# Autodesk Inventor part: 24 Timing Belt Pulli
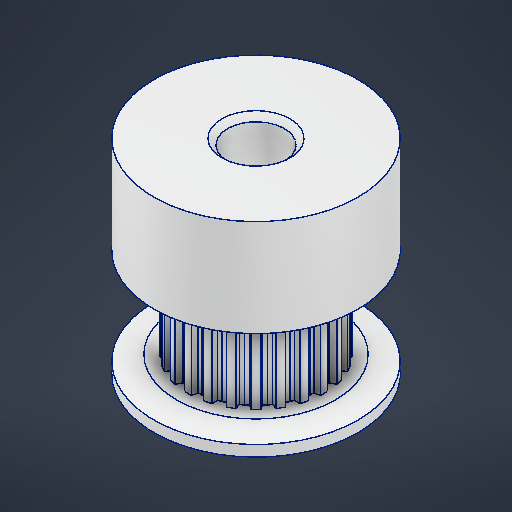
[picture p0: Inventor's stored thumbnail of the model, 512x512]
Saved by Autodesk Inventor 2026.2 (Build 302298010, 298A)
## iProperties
Created: 2026-04
Part Number: 24 Timing Belt Pulli
Material: 알루미늄 6061
Document SubType Name: Modeling
Designer: work
Density: 2.7 g/cm^3
Appearance: 알루미늄 - 평지
Author: work
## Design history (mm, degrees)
sketch "스케치1"
  geometry: C1 r 9 at (0, 0); C2 r 2.5 at (0, 0); 1 further point
  constraints: 2 centre point, 2 coincident
  dimensions: "d0" = 18 diameter of C1; "d1" = 5 diameter of C2
extrude "돌출1" new body sketch "스케치1" distance "d2" = 18; taper "d3" = 0 deg
node "작업 평면1"
sketch "스케치2"
  geometry: L1 (0, 0)-(0, -6); L2 (0, -6)-(0.305, -6); L3 (0.305, -6)-(0.393, -5.5); L4 (0.393, -5.5)-(0.785, -5.5); L5 (0, -6)-(-0.305, -6); L6 (-0.305, -6)-(-0.393, -5.5); L7 (-0.393, -5.5)-(-0.785, -5.5); L8 (0, 0)-(1.553, -5.796); L9 (1.553, -5.796)-(1.847, -5.717); L10 (1.847, -5.717)-(1.803, -5.211); L11 (1.803, -5.211)-(2.182, -5.109); L12 (1.553, -5.796)-(1.259, -5.874); L13 (1.259, -5.874)-(1.044, -5.414); L14 (1.044, -5.414)-(0.665, -5.516); L15 (0, 0)-(3, -5.196); L16 (3, -5.196)-(3.264, -5.044); L17 (3.264, -5.044)-(3.09, -4.567); L18 (3.09, -4.567)-(3.43, -4.37); L19 (3, -5.196)-(2.736, -5.348); L20 (2.736, -5.348)-(2.41, -4.959); L21 (2.41, -4.959)-(2.07, -5.156); L22 (0, 0)-(4.243, -4.243); L23 (4.243, -4.243)-(4.458, -4.027); L24 (4.458, -4.027)-(4.167, -3.611); L25 (4.167, -3.611)-(4.444, -3.334); L26 (4.243, -4.243)-(4.027, -4.458); L27 (4.027, -4.458)-(3.611, -4.167); L28 (3.611, -4.167)-(3.334, -4.444); L29 (0, 0)-(5.196, -3); L30 (5.196, -3)-(5.348, -2.736); L31 (5.348, -2.736)-(4.959, -2.41); L32 (4.959, -2.41)-(5.156, -2.07); L33 (5.196, -3)-(5.044, -3.264); L34 (5.044, -3.264)-(4.567, -3.09); L35 (4.567, -3.09)-(4.37, -3.43); L36 (0, 0)-(5.796, -1.553); L37 (5.796, -1.553)-(5.874, -1.259); L38 (5.874, -1.259)-(5.414, -1.044); L39 (5.414, -1.044)-(5.516, -0.665); L40 (5.796, -1.553)-(5.717, -1.847); L41 (5.717, -1.847)-(5.211, -1.803); L42 (5.211, -1.803)-(5.109, -2.182); L43 (0, 0)-(6, 0); L44 (6, 0)-(6, 0.305); L45 (6, 0.305)-(5.5, 0.393); L46 (5.5, 0.393)-(5.5, 0.785); L47 (6, 0)-(6, -0.305); L48 (6, -0.305)-(5.5, -0.393); L49 (5.5, -0.393)-(5.5, -0.785); L50 (0, 0)-(5.796, 1.553); L51 (5.796, 1.553)-(5.717, 1.847); L52 (5.717, 1.847)-(5.211, 1.803); L53 (5.211, 1.803)-(5.109, 2.182); L54 (5.796, 1.553)-(5.874, 1.259); L55 (5.874, 1.259)-(5.414, 1.044); L56 (5.414, 1.044)-(5.516, 0.665); L57 (0, 0)-(5.196, 3); L58 (5.196, 3)-(5.044, 3.264); L59 (5.044, 3.264)-(4.567, 3.09); L60 (4.567, 3.09)-(4.37, 3.43); L61 (5.196, 3)-(5.348, 2.736); L62 (5.348, 2.736)-(4.959, 2.41); L63 (4.959, 2.41)-(5.156, 2.07); L64 (0, 0)-(4.243, 4.243)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; C1 r 9 at (0, 0) reference; C2 r 2.5 at (0, 0) reference; 25 further points
  constraints: 336 end point, 3 symmetric about line, 2 coincident, 1 parallel, 1 perpendicular, 1 vertical, 359 other
  dimensions: "d5" = 1.5708 distance of L4.end L7.end; "d6" = 6 distance of L1.start L1.end; "d7" = 100 deg angle of L3 L2; "d8" = 0.3927 distance of L3.end L4.end (= 0.25 x d5); "d9" = 0.5 vertical distance of L3.end L2.end; "d12" = 360 deg dimension on L1.start L1.end (derived)
extrude "돌출2" cut sketch "스케치2" distance "d14" = 7.4; taper "d15" = 0 deg
sketch "스케치3" dims "d17" = 2.5
  geometry: L1 (-2.5, 18)-(2.5, 18) reference; L2 (0, 18)-(0, 14); L3 (0, 14)-(0, 12.75); 1 further point
  constraints: 4 end point, 2 vertical, 1 midpoint, 1 vertical alignment, 2 other
  dimensions: "d16" = 4 distance of L2.start L2.end
extrude "돌출3" cut sketch "스케치3" extent not by distance; stored distance "d18" = 7.4; taper "d19" = 0 deg
chamfer "모따기1" distance "d20" = 1.5; stored, may be unused: second distance "d21" = 2, angle "d22" = 45 deg
feature "스레드1" dims "d23" = 5.335, "d24" = 0
chamfer "모따기4" distance "d34" = 2; stored, may be unused: second distance "d35" = 2, angle "d36" = 15 deg
chamfer "모따기3" distance "d31" = 2; stored, may be unused: second distance "d32" = 2, angle "d33" = 15 deg
chamfer "모따기2" distance "d28" = 0.5; stored, may be unused: second distance "d29" = 2, angle "d30" = 45 deg
node "솔리드1"
pattern_circular "원형 패턴1" dims "d26" = 360 deg
node "투영된 루프1"
node "스케치 - 원형 패턴1" dims "d12" = 360 deg (derived)
feature "A9D066F2-1C7D-4E18-AEED-F7BC21143FA4" dims "d23" = 5.335, "d24" = 0
other parameters: "d4" = -1.5
